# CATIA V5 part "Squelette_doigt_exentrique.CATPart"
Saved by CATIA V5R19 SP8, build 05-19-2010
Part number: Squelette doigt exentrique
Publications: "Droite.1", "Plan.1", "Plan.2", "Plan.3", "Droite.2", "Point.2"
Bounding box of the stored display mesh (mm): x -24 to 0, y 0 to 14, z -4 to 4
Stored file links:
  C:\Users\ThinkMotion\Desktop\EU_thinkMotion\iao\IAO_MMS_Groupe3\ecartoux\projet_IAO_ecartoux\projet_IAO_ecartoux\griffe_d'une_camera_ecartoux\Squelette_doigt_exentrique.CATPart
  C:\Users\ThinkMotion\Desktop\EU_thinkMotion\iao\IAO_MMS_Groupe3\ecartoux\projet_IAO_ecartoux\projet_IAO_ecartoux\griffe_d'une_camera_ecartoux\Squelette.CATProduct
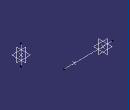
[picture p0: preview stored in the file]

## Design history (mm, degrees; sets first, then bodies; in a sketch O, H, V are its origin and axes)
Set1
  Point1: linked copy from another document
  Point2: linked copy from another document
  Plane1 to Plane3: linked copy from another document
  Point3: linked copy from another document
Set2 "Set géométrique"
  Line1: type PtPt, FirstPoint Point1, SecondPoint Point2, Start 4, End 4
  Plane4: type OffsetPt, RefPlane Plane1, RefPoint Point2
  Plane5 "Plan.2": type OffsetPt, RefPlane Plane2, RefPoint Point2
  Plane6 "Plan.3": type OffsetPt, RefPlane Plane3, RefPoint Point2
  Line2: type PtDir, RefPoint Point3, Direction Plane3, Start -4, End 4
Body1 (main body)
